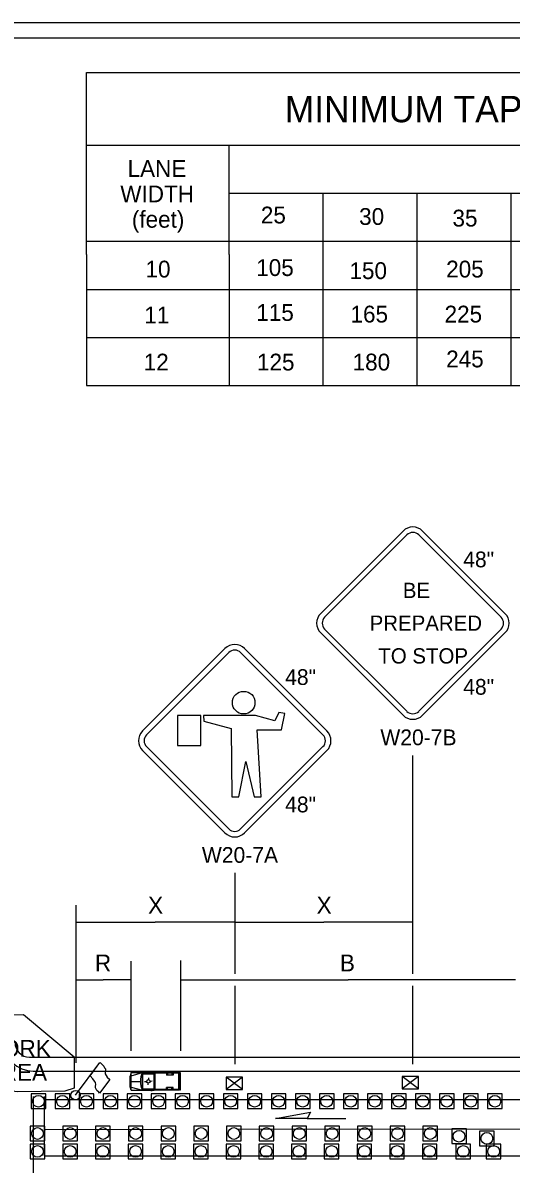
# Model space of a CAD drawing. Extents: x 99988 to 100172, y 99995 to 100047.
# Drawn here: x 100005.501 to 100007.533, y 100005.686 to 100010.437 of the extents above; entities that cross this region are included whole.
import ezdxf

# ---------------------------------------------------------------- set-up
doc = ezdxf.new("R2010")
doc.units = 0
for name, color, linetype in [('Default', 7, 'Continuous'), ('Level 15', 7, 'Continuous'), ('Level 20', 7, 'Continuous'), ('SH_DE_DetailBody1Text', 7, 'Continuous'), ('SH_GI_PlotLimits', 7, 'Continuous'), ('SH_GI_SheetBorder', 7, 'Continuous'), ('SH_GI_TrafficMvmntArrowRt1Lane', 7, 'Continuous'), ('SH_TI_MinTaperLength25to70Note', 7, 'Continuous'), ('SH_TI_SignSpacing35to70Note', 7, 'Continuous'), ('TR_SN_WarningSigns', 7, 'Continuous'), ('TR_WZ_FlaggingStation', 7, 'Continuous'), ('TR_WZ_TrafficSafetyCone', 7, 'Continuous'), ('TR_WZ_TruckBuffer', 7, 'Continuous'), ('TR_WZ_WorkZoneDetails', 7, 'Continuous')]:
    doc.layers.add(name, color=color, linetype=linetype)

msp = doc.modelspace()

# ---------------------------------------------------------------- linework, layer by layer
at = {"layer": 'Default'}
for p, q in [((100006.4156, 100005.9965), (100006.3466, 100006.0481)), ((100006.4156, 100006.0481), (100006.3466, 100005.9965)), ((100007.1479, 100005.9997), (100007.079, 100006.0513)), ((100007.1479, 100006.0513), (100007.079, 100005.9997)), ((100006.3811, 100006.0223), (100006.3811, 100006.0223)), ((100006.3812, 100006.0222), (100006.3812, 100006.0222)), ((100007.1135, 100006.0255), (100007.1135, 100006.0255)), ((100007.1136, 100006.0254), (100007.1136, 100006.0254)), ((100006.0893, 100005.8313), (100005.5945, 100005.829)), ((100010.4792, 100005.833), (100006.3963, 100005.8313))]:
    msp.add_line(p, q, dxfattribs=at)
for points in [[(100005.3343, 100006.3083), (100005.5028, 100006.3097), (100005.714, 100006.133), (100005.714, 100006.003), (100005.6756, 100005.9908), (100005.4791, 100005.9876), (100005.4029, 100005.9966), (100005.3447, 100006.0286), (100005.3044, 100006.0632), (100005.2813, 100006.1074), (100005.2736, 100006.1272)], [(100006.4156, 100005.9965), (100006.4156, 100006.0481), (100006.3466, 100006.0481), (100006.3466, 100005.9965)], [(100007.1479, 100005.9997), (100007.1479, 100006.0513), (100007.079, 100006.0513), (100007.079, 100005.9997)]]:
    msp.add_lwpolyline(points, close=True, dxfattribs=at)
at = {"layer": 'Level 15'}
for p, q in [((100005.7208, 100006.6943), (100006.0518, 100006.6943)), ((100006.3827, 100006.6943), (100006.0518, 100006.6943)), ((100006.3827, 100006.6943), (100006.7533, 100006.6943)), ((100007.124, 100006.6943), (100006.7533, 100006.6943)), ((100005.7208, 100006.4539), (100005.8356, 100006.4539)), ((100005.9504, 100006.4539), (100005.8356, 100006.4539)), ((100006.1575, 100006.4539), (100006.8541, 100006.4539)), ((100007.5506, 100006.4539), (100006.8541, 100006.4539))]:
    msp.add_line(p, q, dxfattribs=at)
at = {"layer": 'SH_GI_PlotLimits'}
msp.add_lwpolyline([(99999.3125, 99999.9375), (100015.8125, 99999.9375), (100015.8125, 100010.4375), (99999.3125, 100010.4375)], close=True, dxfattribs=at)
at = {"layer": 'SH_GI_SheetBorder'}
msp.add_line((100000, 100010.375), (100015.75, 100010.375), dxfattribs=at)
at = {"layer": 'SH_GI_TrafficMvmntArrowRt1Lane'}
msp.add_line((100006.6836, 100005.8766), (100006.8444, 100005.8766), dxfattribs=at)
msp.add_lwpolyline([(100006.5526, 100005.8766), (100006.6985, 100005.9023), (100006.6836, 100005.8766)], close=True, dxfattribs=at)
at = {"layer": 'SH_TI_MinTaperLength25to70Note'}
for p, q in [((100005.766, 100009.9279), (100010.2661, 100009.9279)), ((100006.3592, 100009.4728), (100006.3592, 100009.9279)), ((100006.3592, 100009.7279), (100010.2661, 100009.7279)), ((100006.7498, 100009.7279), (100006.7498, 100008.9279)), ((100007.1405, 100009.7279), (100007.1405, 100008.9279)), ((100007.5312, 100009.7279), (100007.5312, 100008.9279)), ((100005.766, 100009.5279), (100010.2661, 100009.5279)), ((100006.3592, 100009.4728), (100006.3592, 100008.9279)), ((100005.766, 100009.3279), (100010.2661, 100009.3279)), ((100005.766, 100009.1279), (100010.2661, 100009.1279))]:
    msp.add_line(p, q, dxfattribs=at)
at = {"layer": 'SH_TI_SignSpacing35to70Note'}
for p, q in [((100005.766, 100010.2311), (100010.2661, 100010.2311)), ((100005.766, 100009.4728), (100005.766, 100010.2311)), ((100005.766, 100009.4728), (100005.766, 100008.9279)), ((100005.766, 100008.9279), (100010.2661, 100008.9279))]:
    msp.add_line(p, q, dxfattribs=at)
at = {"layer": 'TR_SN_WarningSigns'}
for p, q in [((100006.7405, 100007.9793), (100007.0832, 100008.322)), ((100006.7568, 100007.963), (100007.0995, 100008.3057)), ((100007.1485, 100008.3057), (100007.4912, 100007.963)), ((100007.1648, 100008.322), (100007.5075, 100007.9793)), ((100007.0832, 100007.555), (100006.7405, 100007.8977)), ((100007.0995, 100007.5714), (100006.7568, 100007.914)), ((100007.4912, 100007.914), (100007.1485, 100007.5714)), ((100007.5075, 100007.8977), (100007.1648, 100007.555)), ((100005.9993, 100007.4896), (100006.3419, 100007.8323)), ((100006.0156, 100007.4733), (100006.3583, 100007.816)), ((100006.4072, 100007.816), (100006.7499, 100007.4733)), ((100006.4235, 100007.8323), (100006.7662, 100007.4896)), ((100006.3583, 100007.0817), (100006.0156, 100007.4244)), ((100006.7499, 100007.4244), (100006.4072, 100007.0817)), ((100006.3419, 100007.0654), (100005.9993, 100007.408)), ((100006.7662, 100007.408), (100006.4235, 100007.0654))]:
    msp.add_line(p, q, dxfattribs=at)
for points in [[(100006.2528, 100007.5541), (100006.2542, 100007.53), (100006.3682, 100007.5001), (100006.3707, 100007.2157), (100006.4003, 100007.2157), (100006.4285, 100007.3622), (100006.464, 100007.2154), (100006.4926, 100007.2154), (100006.4764, 100007.4943), (100006.5774, 100007.4943), (100006.5912, 100007.5621), (100006.5655, 100007.567), (100006.5491, 100007.5323), (100006.4687, 100007.5541)], [(100006.1441, 100007.5538), (100006.1441, 100007.4291), (100006.2414, 100007.4291), (100006.2414, 100007.5538)]]:
    msp.add_lwpolyline(points, close=True, dxfattribs=at)
msp.add_circle((100006.4198, 100007.6075), 0.0471, dxfattribs=at)
for centre, radius, start, end in [((100007.124, 100008.2812), 0.0577, 44.9963, 134.9997), ((100007.124, 100008.2812), 0.0346, 44.9963, 134.9997), ((100006.7813, 100007.9385), 0.0577, 134.9966, 224.9936), ((100006.7813, 100007.9385), 0.0346, 134.9966, 224.9936), ((100007.4667, 100007.9385), 0.0346, 314.9994, 44.9948), ((100007.4667, 100007.9385), 0.0577, 314.9994, 44.9948), ((100006.3827, 100007.7915), 0.0577, 44.9963, 134.9997), ((100006.3827, 100007.7915), 0.0346, 44.9963, 134.9997), ((100007.124, 100007.5958), 0.0346, 225, 314.9996), ((100007.124, 100007.5958), 0.0577, 225, 314.9996), ((100006.04, 100007.4488), 0.0577, 134.9966, 224.9936), ((100006.04, 100007.4488), 0.0346, 134.9966, 224.9936), ((100006.7254, 100007.4488), 0.0346, 314.9994, 44.9948), ((100006.7254, 100007.4488), 0.0577, 314.9994, 44.9948), ((100006.3827, 100007.1062), 0.0577, 225, 314.9996), ((100006.3827, 100007.1062), 0.0346, 225, 314.9996)]:
    msp.add_arc(centre, radius, start, end, dxfattribs=at)
at = {"layer": 'TR_WZ_FlaggingStation'}
for p, q in [((100005.7202, 100005.9734), (100005.8212, 100006.1098)), ((100005.7802, 100006.0544), (100005.8213, 100006.1099)), ((100005.7802, 100006.0544), (100005.7802, 100006.0544)), ((100005.8622, 100006.0393), (100005.8201, 100005.9824))]:
    msp.add_line(p, q, dxfattribs=at)
for points in [[(100005.8213, 100006.1099), (100005.8239, 100006.1075), (100005.8321, 100006.1004), (100005.838, 100006.0941), (100005.8412, 100006.088), (100005.8442, 100006.083), (100005.8451, 100006.0778), (100005.845, 100006.0724), (100005.8434, 100006.0691), (100005.8434, 100006.0627), (100005.8468, 100006.0555), (100005.8517, 100006.0491), (100005.8622, 100006.0393)], [(100005.8201, 100005.9824), (100005.8163, 100005.9856), (100005.8085, 100005.9933), (100005.8035, 100006.0035), (100005.8033, 100006.0109), (100005.8044, 100006.0174), (100005.8029, 100006.0258), (100005.7991, 100006.0323), (100005.7922, 100006.0412), (100005.7802, 100006.0544)]]:
    msp.add_lwpolyline(points, dxfattribs=at)
msp.add_circle((100005.7202, 100005.9734), 0.0195, dxfattribs=at)
at = {"layer": 'TR_WZ_TrafficSafetyCone'}
for points in [[(100005.5352, 100005.9178), (100005.5959, 100005.9178), (100005.5959, 100005.9786), (100005.5352, 100005.9786)], [(100005.6352, 100005.9178), (100005.6959, 100005.9178), (100005.6959, 100005.9786), (100005.6352, 100005.9786)], [(100005.7352, 100005.9178), (100005.7959, 100005.9178), (100005.7959, 100005.9786), (100005.7352, 100005.9786)], [(100005.8352, 100005.9178), (100005.8959, 100005.9178), (100005.8959, 100005.9786), (100005.8352, 100005.9786)], [(100005.9352, 100005.9178), (100005.9959, 100005.9178), (100005.9959, 100005.9786), (100005.9352, 100005.9786)], [(100006.0352, 100005.9178), (100006.0959, 100005.9178), (100006.0959, 100005.9786), (100006.0352, 100005.9786)], [(100006.1352, 100005.9178), (100006.1959, 100005.9178), (100006.1959, 100005.9786), (100006.1352, 100005.9786)], [(100006.2352, 100005.9178), (100006.2959, 100005.9178), (100006.2959, 100005.9786), (100006.2352, 100005.9786)], [(100006.3352, 100005.9178), (100006.3959, 100005.9178), (100006.3959, 100005.9786), (100006.3352, 100005.9786)], [(100006.4352, 100005.9178), (100006.4959, 100005.9178), (100006.4959, 100005.9786), (100006.4352, 100005.9786)], [(100006.5352, 100005.9178), (100006.5959, 100005.9178), (100006.5959, 100005.9786), (100006.5352, 100005.9786)], [(100006.6352, 100005.9178), (100006.6959, 100005.9178), (100006.6959, 100005.9786), (100006.6352, 100005.9786)], [(100006.7352, 100005.9178), (100006.7959, 100005.9178), (100006.7959, 100005.9786), (100006.7352, 100005.9786)], [(100006.8352, 100005.9178), (100006.8959, 100005.9178), (100006.8959, 100005.9786), (100006.8352, 100005.9786)], [(100006.9352, 100005.9178), (100006.9959, 100005.9178), (100006.9959, 100005.9786), (100006.9352, 100005.9786)], [(100007.0352, 100005.9178), (100007.0959, 100005.9178), (100007.0959, 100005.9786), (100007.0352, 100005.9786)], [(100007.1352, 100005.9178), (100007.1959, 100005.9178), (100007.1959, 100005.9786), (100007.1352, 100005.9786)], [(100007.2352, 100005.9178), (100007.2959, 100005.9178), (100007.2959, 100005.9786), (100007.2352, 100005.9786)], [(100007.3352, 100005.9178), (100007.3959, 100005.9178), (100007.3959, 100005.9786), (100007.3352, 100005.9786)], [(100007.4352, 100005.9178), (100007.4959, 100005.9178), (100007.4959, 100005.9786), (100007.4352, 100005.9786)], [(100005.5312, 100005.7837), (100005.5919, 100005.7837), (100005.5919, 100005.8444), (100005.5312, 100005.8444)], [(100005.6674, 100005.7837), (100005.7282, 100005.7837), (100005.7282, 100005.8444), (100005.6674, 100005.8444)], [(100005.8037, 100005.7837), (100005.8644, 100005.7837), (100005.8644, 100005.8444), (100005.8037, 100005.8444)], [(100005.9399, 100005.7837), (100006.0007, 100005.7837), (100006.0007, 100005.8444), (100005.9399, 100005.8444)], [(100006.0762, 100005.7837), (100006.1369, 100005.7837), (100006.1369, 100005.8444), (100006.0762, 100005.8444)], [(100006.2124, 100005.7837), (100006.2732, 100005.7837), (100006.2732, 100005.8444), (100006.2124, 100005.8444)], [(100006.3487, 100005.7837), (100006.4094, 100005.7837), (100006.4094, 100005.8444), (100006.3487, 100005.8444)], [(100006.4849, 100005.7837), (100006.5456, 100005.7837), (100006.5456, 100005.8444), (100006.4849, 100005.8444)], [(100006.6212, 100005.7837), (100006.6819, 100005.7837), (100006.6819, 100005.8444), (100006.6212, 100005.8444)], [(100006.7574, 100005.7837), (100006.8181, 100005.7837), (100006.8181, 100005.8444), (100006.7574, 100005.8444)], [(100006.8936, 100005.7837), (100006.9544, 100005.7837), (100006.9544, 100005.8444), (100006.8936, 100005.8444)], [(100007.0299, 100005.7837), (100007.0906, 100005.7837), (100007.0906, 100005.8444), (100007.0299, 100005.8444)], [(100007.1661, 100005.7837), (100007.2269, 100005.7837), (100007.2269, 100005.8444), (100007.1661, 100005.8444)], [(100007.2859, 100005.7722), (100007.3467, 100005.7722), (100007.3467, 100005.833), (100007.2859, 100005.833)], [(100007.4016, 100005.7633), (100007.4624, 100005.7633), (100007.4624, 100005.824), (100007.4016, 100005.824)], [(100005.5312, 100005.709), (100005.5919, 100005.709), (100005.5919, 100005.7698), (100005.5312, 100005.7698)], [(100005.6672, 100005.709), (100005.728, 100005.709), (100005.728, 100005.7698), (100005.6672, 100005.7698)], [(100005.8033, 100005.709), (100005.864, 100005.709), (100005.864, 100005.7698), (100005.8033, 100005.7698)], [(100005.9393, 100005.709), (100006.0001, 100005.709), (100006.0001, 100005.7698), (100005.9393, 100005.7698)], [(100006.0754, 100005.709), (100006.1361, 100005.709), (100006.1361, 100005.7698), (100006.0754, 100005.7698)], [(100006.2114, 100005.709), (100006.2721, 100005.709), (100006.2721, 100005.7698), (100006.2114, 100005.7698)], [(100006.3474, 100005.709), (100006.4082, 100005.709), (100006.4082, 100005.7698), (100006.3474, 100005.7698)], [(100006.4835, 100005.709), (100006.5442, 100005.709), (100006.5442, 100005.7698), (100006.4835, 100005.7698)], [(100006.6195, 100005.709), (100006.6802, 100005.709), (100006.6802, 100005.7698), (100006.6195, 100005.7698)], [(100006.7555, 100005.709), (100006.8163, 100005.709), (100006.8163, 100005.7698), (100006.7555, 100005.7698)], [(100006.8916, 100005.709), (100006.9523, 100005.709), (100006.9523, 100005.7698), (100006.8916, 100005.7698)], [(100007.0276, 100005.709), (100007.0884, 100005.709), (100007.0884, 100005.7698), (100007.0276, 100005.7698)], [(100007.1637, 100005.709), (100007.2244, 100005.709), (100007.2244, 100005.7698), (100007.1637, 100005.7698)], [(100007.3032, 100005.709), (100007.3639, 100005.709), (100007.3639, 100005.7698), (100007.3032, 100005.7698)], [(100007.4298, 100005.709), (100007.4906, 100005.709), (100007.4906, 100005.7698), (100007.4298, 100005.7698)]]:
    msp.add_lwpolyline(points, close=True, dxfattribs=at)
for centre in [(100005.5655, 100005.9482), (100005.6655, 100005.9482), (100005.7655, 100005.9482), (100005.8655, 100005.9482), (100005.9655, 100005.9482), (100006.0655, 100005.9482), (100006.1655, 100005.9482), (100006.2655, 100005.9482), (100006.3655, 100005.9482), (100006.4655, 100005.9482), (100006.5655, 100005.9482), (100006.6655, 100005.9482), (100006.7655, 100005.9482), (100006.8655, 100005.9482), (100006.9655, 100005.9482), (100007.0655, 100005.9482), (100007.1655, 100005.9482), (100007.2655, 100005.9482), (100007.3655, 100005.9482), (100007.4655, 100005.9482), (100005.5616, 100005.814), (100005.6978, 100005.814), (100005.8341, 100005.814), (100005.9703, 100005.814), (100006.1065, 100005.814), (100006.2428, 100005.814), (100006.379, 100005.814), (100006.5153, 100005.814), (100006.6515, 100005.814), (100006.7878, 100005.814), (100006.924, 100005.814), (100007.0603, 100005.814), (100007.1965, 100005.814), (100007.3163, 100005.8026), (100007.432, 100005.7936), (100005.5616, 100005.7394), (100005.6976, 100005.7394), (100005.8336, 100005.7394), (100005.9697, 100005.7394), (100006.1057, 100005.7394), (100006.2418, 100005.7394), (100006.3778, 100005.7394), (100006.5138, 100005.7394), (100006.6499, 100005.7394), (100006.7859, 100005.7394), (100006.922, 100005.7394), (100007.058, 100005.7394), (100007.194, 100005.7394), (100007.3336, 100005.7394), (100007.4602, 100005.7394)]:
    msp.add_circle(centre, 0.0244, dxfattribs=at)
at = {"layer": 'TR_WZ_TruckBuffer'}
for p, q in [((100005.9514, 100006.068), (100005.9467, 100006.053)), ((100005.9467, 100006.0089), (100005.9467, 100006.053)), ((100005.9514, 100005.994), (100005.9514, 100006.068)), ((100005.9514, 100006.068), (100006.0469, 100006.068)), ((100005.9514, 100006.0544), (100005.9991, 100006.068)), ((100005.9991, 100005.994), (100005.9991, 100006.068)), ((100006, 100005.994), (100006, 100006.068)), ((100006.0051, 100006.0623), (100006, 100006.068)), ((100006, 100006.0623), (100006.0469, 100006.0623)), ((100006.0233, 100006.0452), (100006.0232, 100006.0396)), ((100006.0339, 100006.069), (100006.0396, 100006.069)), ((100006.0469, 100005.994), (100006.0469, 100006.068)), ((100006.1524, 100006.068), (100006.0483, 100006.068)), ((100006.0483, 100005.994), (100006.0483, 100006.068)), ((100006.1494, 100006.065), (100006.0513, 100006.065)), ((100006.0513, 100005.9969), (100006.0513, 100006.065)), ((100006.0982, 100006.065), (100006.0982, 100006.0565)), ((100006.126, 100006.0565), (100006.0982, 100006.0565)), ((100006.1032, 100006.065), (100006.1032, 100006.0565)), ((100006.1204, 100006.065), (100006.1204, 100006.0565)), ((100006.126, 100006.065), (100006.126, 100006.0565)), ((100006.1494, 100005.9969), (100006.1494, 100006.065)), ((100006.1524, 100005.994), (100006.1524, 100006.068)), ((100006.155, 100006.0668), (100006.1527, 100006.0668)), ((100006.1527, 100005.9952), (100006.1527, 100006.0668)), ((100006.1573, 100005.9974), (100006.1573, 100006.0645)), ((100005.9514, 100005.994), (100005.9467, 100006.0089)), ((100005.9514, 100006.031), (100005.9898, 100006.031)), ((100005.9514, 100006.0075), (100005.9991, 100005.994)), ((100006, 100005.994), (100006.0061, 100005.9997)), ((100006, 100005.9997), (100006.0469, 100005.9997)), ((100006.0077, 100006.0309), (100006.0141, 100006.0309)), ((100006.0229, 100006.0163), (100006.0229, 100006.0223)), ((100006.0301, 100006.0311), (100006.0301, 100006.0311)), ((100006.0386, 100006.0313), (100006.031, 100006.0311)), ((100006.1494, 100005.9969), (100006.0513, 100005.9969)), ((100006.126, 100006.0054), (100006.0982, 100006.0054)), ((100006.0982, 100005.9969), (100006.0982, 100006.0054)), ((100006.1032, 100005.9969), (100006.1032, 100006.0054)), ((100006.1204, 100005.9969), (100006.1204, 100006.0054)), ((100006.126, 100005.9969), (100006.126, 100006.0054)), ((100006.1573, 100006.0362), (100006.1527, 100006.0348)), ((100006.1573, 100006.0258), (100006.1527, 100006.0272)), ((100006.156, 100006.031), (100006.154, 100006.031)), ((100006.155, 100006.0299), (100006.155, 100006.032)), ((100005.9514, 100005.994), (100006.0469, 100005.994)), ((100006.0339, 100005.9929), (100006.0396, 100005.9929)), ((100006.1524, 100005.994), (100006.0483, 100005.994)), ((100006.155, 100005.9952), (100006.1527, 100005.9952))]:
    msp.add_line(p, q, dxfattribs=at)
for centre, radius in [((100006.0229, 100006.031), 0.00713), ((100006.155, 100006.031), 0.00104)]:
    msp.add_circle(centre, radius, dxfattribs=at)
for centre, radius, start, end in [((100006.0674, 100006.031), 0.0777, 151.5505, 208.46), ((100006.155, 100006.0645), 0.00226, 0, 90), ((100006.155, 100005.9974), 0.00226, 270, 360)]:
    msp.add_arc(centre, radius, start, end, dxfattribs=at)
at = {"layer": 'TR_WZ_WorkZoneDetails'}
for p, q in [((100007.124, 100006.4789), (100007.124, 100007.3881)), ((100006.3827, 100006.8985), (100006.3827, 100006.4789)), ((100005.7208, 100006.7643), (100005.7208, 100006.1088)), ((100005.9504, 100006.5317), (100005.9504, 100006.1574)), ((100006.1575, 100006.5339), (100006.1575, 100006.1574)), ((100006.3827, 100006.4289), (100006.3827, 100006.1031)), ((100007.124, 100006.1031), (100007.124, 100006.4289)), ((100005.5287, 100006.1318), (100007.2729, 100006.1318)), ((100007.2729, 100006.1318), (100008.0987, 100006.1318)), ((100005.5438, 100006.0731), (100005.7348, 100006.0731)), ((100005.7348, 100006.0731), (100006.1636, 100006.0731)), ((100006.1636, 100006.0731), (100007.2729, 100006.0731)), ((100007.2729, 100006.0731), (100008.1042, 100006.0731)), ((100005.5447, 100005.3691), (100005.5447, 100005.9676)), ((100005.5914, 100005.7212), (100005.5914, 100005.9676)), ((100005.5914, 100005.9557), (100010.4791, 100005.9557)), ((100005.5945, 100005.7212), (100010.4791, 100005.7212))]:
    msp.add_line(p, q, dxfattribs=at)
for centre, radius in [((100005.5438, 100006.1943), 0.1212), ((100005.5287, 100006.1924), 0.0606)]:
    msp.add_arc(centre, radius, 180, 270, dxfattribs=at)

# ---------------------------------------------------------------- texts
at = {"layer": 'Level 20'}
for s, p in [('X', (100006.022, 100006.7293)), ('X', (100006.7236, 100006.7293)), ('R', (100005.8006, 100006.4889)), ('B', (100006.8204, 100006.4889))]:
    msp.add_text(s, height=0.07, rotation=360, dxfattribs=at).set_placement(p)
at = {"layer": 'SH_DE_DetailBody1Text'}
for s, p in [('WORK', (100005.3258, 100006.1335)), ('AREA', (100005.3465, 100006.0335))]:
    msp.add_text(s, height=0.07, rotation=360, dxfattribs=at).set_placement(p)
at = {"layer": 'SH_TI_MinTaperLength25to70Note'}
for s, height, p in [('MINIMUM TAPER LENGTH = L (feet)', 0.11, (100006.591, 100010.0235)), ('LANE', 0.07, (100005.9366, 100009.7958)), ('WIDTH', 0.07, (100005.9063, 100009.6902)), ('(feet)', 0.07, (100005.9544, 100009.5846)), ('25', 0.07, (100006.4913, 100009.6024)), ('30', 0.07, (100006.9004, 100009.5962)), ('35', 0.07, (100007.2889, 100009.5896)), ('10', 0.07, (100006.0112, 100009.3774)), ('105', 0.07, (100006.4721, 100009.3836)), ('150', 0.07, (100006.8601, 100009.3708)), ('205', 0.07, (100007.2626, 100009.3774)), ('11', 0.07, (100006.0062, 100009.1862)), ('115', 0.07, (100006.4724, 100009.1966)), ('165', 0.07, (100006.8645, 100009.19)), ('225', 0.07, (100007.2561, 100009.19)), ('12', 0.07, (100006.0038, 100008.9902)), ('125', 0.07, (100006.4752, 100008.9902)), ('180', 0.07, (100006.8732, 100008.9902)), ('245', 0.07, (100007.2626, 100009.0033))]:
    msp.add_text(s, height=height, dxfattribs=at).set_placement(p)
at = {"layer": 'TR_SN_WarningSigns'}
for s, height, p in [('48"', 0.06563, (100007.3336, 100008.1709)), ('BE', 0.0636, (100007.0823, 100008.043)), ('PREPARED', 0.0636, (100006.9441, 100007.9067)), ('TO STOP', 0.0636, (100006.9802, 100007.7704)), ('48"', 0.06563, (100006.5924, 100007.6812)), ('48"', 0.06563, (100007.3336, 100007.6405)), ('W20-7B', 0.06563, (100006.9888, 100007.4303)), ('48"', 0.06563, (100006.5924, 100007.1509)), ('W20-7A', 0.06563, (100006.2459, 100006.9407))]:
    msp.add_text(s, height=height, dxfattribs=at).set_placement(p)

doc.saveas('drawing.dxf')
